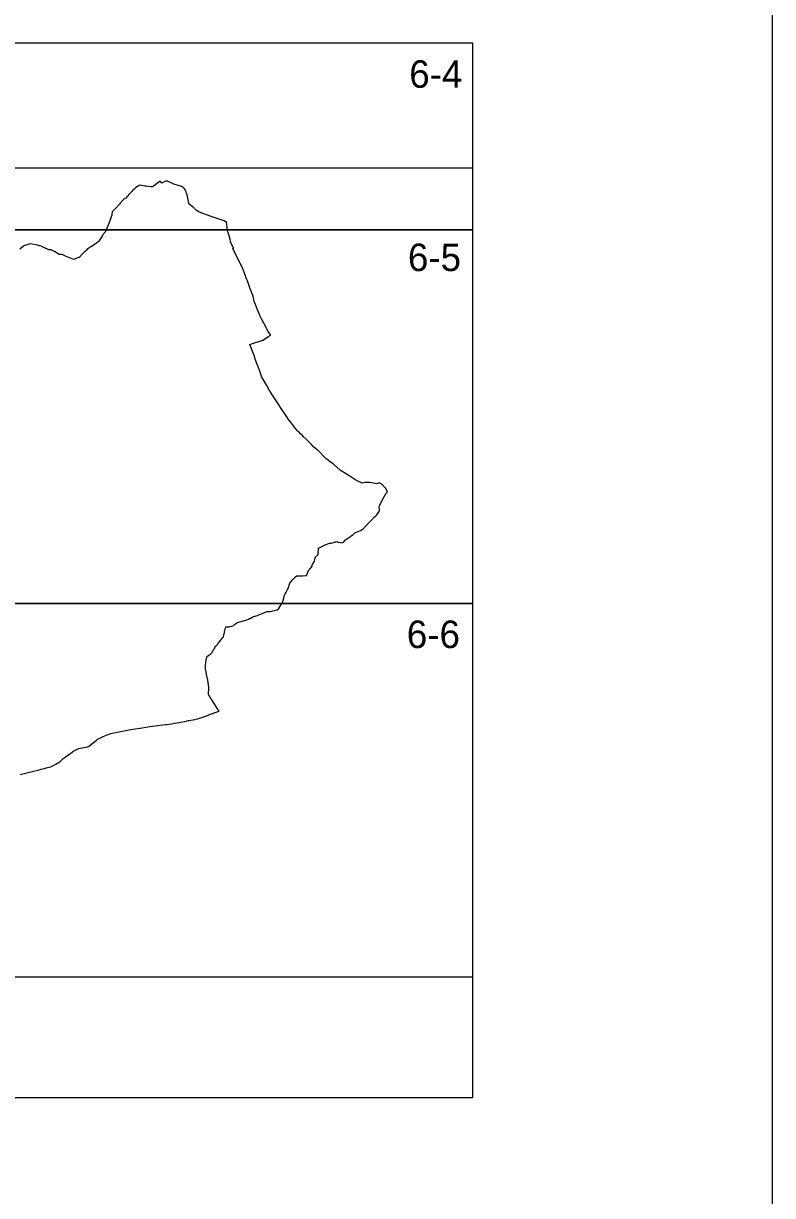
# Model space of a CAD drawing. Extents: x -447352 to -425530, y -1135906 to -1121091.
# Drawn here: x -434917.6 to -434667, y -1126663.9 to -1126271.9 of the extents above; entities that cross this region are included whole.
import ezdxf

# ---------------------------------------------------------------- set-up
doc = ezdxf.new("R2010")
doc.units = 0
for name, color, linetype in [('Vrstva 1', 7, 'Continuous'), ('Vrstva 10', 7, 'Continuous'), ('Vrstva 4', 7, 'Continuous')]:
    doc.layers.add(name, color=color, linetype=linetype)

msp = doc.modelspace()

# ---------------------------------------------------------------- linework, layer by layer
at = {"layer": 'Vrstva 1'}
msp.add_lwpolyline([(-436152.02, -1126016.81), (-436152.02, -1127066.81), (-434667.02, -1127066.81), (-434667.02, -1126016.81)], close=True, dxfattribs=at)
msp.add_lwpolyline([(-434918.73, -1126523.09), (-434915.19, -1126522.22), (-434912.42, -1126521.55), (-434911.75, -1126521.34), (-434910.26, -1126520.98), (-434910.05, -1126520.92), (-434908.62, -1126520.53), (-434908.02, -1126520.27), (-434907.8, -1126520.17), (-434907.64, -1126520.11), (-434906.82, -1126519.66), (-434906.76, -1126519.62), (-434905.45, -1126518.84), (-434904.3, -1126517.79), (-434903.65, -1126517.29), (-434903.52, -1126517.18), (-434903.5, -1126517.17), (-434903.34, -1126517.04), (-434903.19, -1126516.94), (-434902.39, -1126516.38), (-434902.33, -1126516.34), (-434902.26, -1126516.29), (-434901.75, -1126515.94), (-434901.38, -1126515.68), (-434900.72, -1126515.22), (-434900.13, -1126514.81), (-434899.97, -1126514.84), (-434899.96, -1126514.84), (-434899.94, -1126514.82), (-434899.21, -1126514.43), (-434896.25, -1126513.85), (-434895.83, -1126513.7), (-434893.8, -1126512.07), (-434893.33, -1126511.73), (-434893.3, -1126511.71), (-434892.94, -1126511.45), (-434892.76, -1126511.33), (-434891.37, -1126510.63), (-434889.96, -1126509.99), (-434889.66, -1126509.84), (-434888.4, -1126509.38), (-434887.4, -1126509.13), (-434881.69, -1126508.07), (-434880.27, -1126507.81), (-434878.56, -1126507.56), (-434874.69, -1126506.99), (-434874.45, -1126506.96), (-434870.15, -1126506.44), (-434869.62, -1126506.38), (-434867.47, -1126506.02), (-434867.15, -1126505.97), (-434865.49, -1126505.7), (-434865.09, -1126505.63), (-434863.68, -1126505.34), (-434862.39, -1126505.07), (-434862.18, -1126505.03), (-434861.01, -1126504.8), (-434860.34, -1126504.67), (-434860.32, -1126504.67), (-434859.41, -1126504.46), (-434859.34, -1126504.44), (-434858.69, -1126504.28), (-434858.34, -1126504.17), (-434857.45, -1126503.88), (-434857.01, -1126503.73), (-434856.36, -1126503.49), (-434856.24, -1126503.45), (-434855.15, -1126502.96), (-434855.15, -1126502.96), (-434855.03, -1126502.92), (-434854.38, -1126502.69), (-434854.29, -1126502.66), (-434853.86, -1126502.5), (-434852.2, -1126501.92), (-434852.22, -1126501.87), (-434852.33, -1126501.7), (-434852.49, -1126501.47), (-434852.71, -1126501.15), (-434854.41, -1126498.51), (-434854.62, -1126498.16), (-434854.79, -1126497.89), (-434855.23, -1126497.18), (-434855.76, -1126496.33), (-434855.6, -1126493.97), (-434855.59, -1126493.88), (-434855.98, -1126491.58), (-434855.98, -1126491.56), (-434855.99, -1126491.54), (-434855.99, -1126491.54), (-434855.99, -1126491.51), (-434856.4, -1126489.68), (-434856.41, -1126489.49), (-434856.47, -1126488.69), (-434856.57, -1126488.41), (-434856.58, -1126488.39), (-434856.69, -1126488.17), (-434856.73, -1126488.09), (-434856.74, -1126487.71), (-434856.77, -1126487.01), (-434856.72, -1126486.52), (-434856.72, -1126486.5), (-434856.63, -1126485.64), (-434856.61, -1126485.53), (-434856.32, -1126483.89), (-434856.24, -1126483.81), (-434855.94, -1126483.47), (-434855.88, -1126483.4), (-434855.62, -1126483.28), (-434855.56, -1126483.22), (-434855.3, -1126483.02), (-434855.07, -1126482.84), (-434854.86, -1126482.68), (-434854.8, -1126482.64), (-434854.72, -1126482.51), (-434854.64, -1126482.39), (-434854.53, -1126482.22), (-434854.31, -1126481.89), (-434853.89, -1126481.24), (-434853.76, -1126480.99), (-434853.75, -1126480.98), (-434853.61, -1126480.69), (-434853.56, -1126480.6), (-434853.38, -1126480.27), (-434853.24, -1126480.12), (-434852.94, -1126479.81), (-434852.77, -1126479.63), (-434852.49, -1126479.28), (-434852.36, -1126479.11), (-434851.67, -1126478.26), (-434851.01, -1126477.45), (-434850.72, -1126477.09), (-434850.48, -1126475.92), (-434850.42, -1126475.69), (-434850.35, -1126475.41), (-434850.03, -1126474.1), (-434849.95, -1126473.82), (-434849.95, -1126473.79), (-434849.93, -1126473.74), (-434849.77, -1126473.73), (-434849.75, -1126473.73), (-434849.51, -1126473.73), (-434848.82, -1126473.71), (-434848.81, -1126473.71), (-434848.78, -1126473.71), (-434848.1, -1126473.53), (-434847.9, -1126473.47), (-434847.48, -1126473.36), (-434847.46, -1126473.35), (-434847.4, -1126473.29), (-434847.1, -1126473.01), (-434846.98, -1126472.93), (-434846.64, -1126472.67), (-434846.22, -1126472.35), (-434846.15, -1126472.33), (-434845.59, -1126472.17), (-434842.89, -1126471.41), (-434842.3, -1126471.14), (-434841.97, -1126470.98), (-434841.92, -1126470.96), (-434841.82, -1126470.91), (-434841.46, -1126470.73), (-434841.41, -1126470.71), (-434841.38, -1126470.69), (-434841.37, -1126470.69), (-434841.34, -1126470.67), (-434841.03, -1126470.52), (-434840.97, -1126470.48), (-434840.86, -1126470.43), (-434839.78, -1126470.1), (-434839.35, -1126469.92), (-434838.83, -1126469.7), (-434837.82, -1126469.29), (-434836.4, -1126468.66), (-434836.26, -1126468.65), (-434835.13, -1126468.6), (-434832.73, -1126468.04), (-434832.2, -1126467.64), (-434832.13, -1126467.52), (-434832.04, -1126467.34), (-434831.78, -1126466.83), (-434831.43, -1126466.4), (-434831.41, -1126466.37), (-434831.2, -1126466.08), (-434831.09, -1126465.92), (-434831.08, -1126465.91), (-434830.54, -1126464.13), (-434830.53, -1126464.1), (-434830.33, -1126463.15), (-434830.07, -1126462.69), (-434829.88, -1126462.36), (-434829.33, -1126461.24), (-434828.95, -1126460.73), (-434828.92, -1126460.6), (-434828.85, -1126460.3), (-434828.82, -1126460.16), (-434828.76, -1126459.91), (-434828.74, -1126459.81), (-434828.42, -1126458.8), (-434828.41, -1126458.79), (-434828.12, -1126458.51), (-434827.46, -1126457.88), (-434827.41, -1126457.83), (-434826.94, -1126457.35), (-434826.68, -1126457.09), (-434826.58, -1126456.98), (-434826.21, -1126456.66), (-434826.17, -1126456.66), (-434826.16, -1126456.66), (-434825.75, -1126456.65), (-434825.58, -1126456.66), (-434824.95, -1126456.68), (-434824.24, -1126456.68), (-434823.27, -1126456.59), (-434823.24, -1126456.59), (-434822.99, -1126456.56), (-434822.77, -1126456.2), (-434822.72, -1126456.07), (-434822.7, -1126456.02), (-434822.68, -1126455.96), (-434822.32, -1126454.94), (-434822.18, -1126454.77), (-434822.08, -1126454.66), (-434822.04, -1126454.62), (-434821.98, -1126454.54), (-434821.86, -1126454.41), (-434821.59, -1126454.09), (-434821.5, -1126453.99), (-434821.4, -1126453.87), (-434821.06, -1126453.48), (-434820.99, -1126453.09), (-434820.93, -1126452.78), (-434820.86, -1126452.65), (-434820.31, -1126451.73), (-434820.2, -1126451.34), (-434820.01, -1126450.64), (-434819.89, -1126450.35), (-434819.6, -1126450.08), (-434819.05, -1126449.57), (-434818.98, -1126449.51), (-434818.88, -1126447.4), (-434817.86, -1126446.91), (-434817.46, -1126446.7), (-434817.21, -1126446.57), (-434816.92, -1126446.41), (-434816.7, -1126446.33), (-434816.36, -1126446.2), (-434816.31, -1126446.19), (-434815.22, -1126445.78), (-434815.21, -1126445.78), (-434814.72, -1126445.72), (-434814.64, -1126445.7), (-434813.61, -1126445.44), (-434813.46, -1126445.4), (-434813.37, -1126445.37), (-434813.2, -1126445.32), (-434812.67, -1126445.15), (-434812.67, -1126445.15), (-434812.66, -1126445.16), (-434812.66, -1126445.16), (-434812.63, -1126445.22), (-434812.5, -1126445.44), (-434811.62, -1126445.54), (-434811.42, -1126445.56), (-434811.06, -1126445.6), (-434810.97, -1126445.56), (-434810.54, -1126445.38), (-434809.89, -1126444.67), (-434808.25, -1126443.51), (-434808.16, -1126443.44), (-434807.99, -1126443.33), (-434807.48, -1126442.91), (-434806.73, -1126442.31), (-434805.46, -1126441.74), (-434804.84, -1126441.47), (-434804.3, -1126441.23), (-434804.24, -1126441.2), (-434802.59, -1126439.53), (-434801.75, -1126438.64), (-434801.39, -1126438.26), (-434800.2, -1126436.9), (-434799.6, -1126436.44), (-434799.55, -1126436.4), (-434798.71, -1126435.39), (-434798.51, -1126434.82), (-434798.6, -1126433.49), (-434798.38, -1126433), (-434797.74, -1126431.55), (-434796.28, -1126429.07), (-434796.25, -1126429.02), (-434796.25, -1126429.02), (-434796.23, -1126428.99), (-434796.2, -1126428.95), (-434796.05, -1126428.76), (-434795.79, -1126428.42), (-434796.05, -1126428.12), (-434796.19, -1126427.9), (-434796.66, -1126427.16), (-434796.86, -1126426.97), (-434797.01, -1126426.81), (-434797.2, -1126426.61), (-434797.78, -1126426.04), (-434798.63, -1126425.57), (-434799.08, -1126425.75), (-434799.41, -1126425.87), (-434801.16, -1126425.6), (-434801.77, -1126425.51), (-434801.91, -1126425.5), (-434802.5, -1126425.48), (-434802.88, -1126425.43), (-434803.04, -1126425.4), (-434803.08, -1126425.4), (-434803.11, -1126425.39), (-434803.11, -1126425.39), (-434803.14, -1126425.4), (-434803.24, -1126425.43), (-434803.37, -1126425.46), (-434804.27, -1126425.7), (-434804.34, -1126425.67), (-434806.41, -1126424.63), (-434808.43, -1126423.35), (-434811.34, -1126421.53), (-434811.5, -1126421.39), (-434811.54, -1126421.36), (-434811.63, -1126421.28), (-434812.77, -1126420.35), (-434813.92, -1126419.3), (-434814.03, -1126419.2), (-434815.24, -1126418.44), (-434815.52, -1126418.21), (-434816.15, -1126417.71), (-434816.46, -1126417.47), (-434816.96, -1126416.94), (-434817.68, -1126416.18), (-434817.83, -1126416.02), (-434818.29, -1126415.53), (-434819.26, -1126414.5), (-434819.46, -1126414.39), (-434819.46, -1126414.39), (-434819.64, -1126414.3), (-434819.84, -1126414.2), (-434820.67, -1126413.37), (-434821.3, -1126412.74), (-434822.48, -1126411.57), (-434823.41, -1126410.63), (-434823.57, -1126410.48), (-434824.01, -1126410.03), (-434824.25, -1126409.79), (-434824.34, -1126409.7), (-434824.38, -1126409.66), (-434824.9, -1126409.14), (-434825.54, -1126408.49), (-434825.62, -1126408.41), (-434825.64, -1126408.39), (-434825.79, -1126408.24), (-434826.62, -1126407.4), (-434827, -1126406.9), (-434827.28, -1126406.53), (-434827.6, -1126406.1), (-434827.96, -1126405.62), (-434828.91, -1126404.36), (-434829.28, -1126403.82), (-434831.82, -1126400.08), (-434831.99, -1126399.82), (-434832.76, -1126398.63), (-434833.43, -1126397.62), (-434834.27, -1126396.29), (-434835.07, -1126395.02), (-434835.15, -1126394.89), (-434836.24, -1126393.04), (-434837.92, -1126390.19), (-434837.92, -1126390.18), (-434837.92, -1126390.18), (-434837.93, -1126390.18), (-434838.26, -1126389.2), (-434838.71, -1126387.9), (-434838.77, -1126387.7), (-434840.15, -1126384.19), (-434840.44, -1126382.94), (-434841.92, -1126379.26), (-434841.29, -1126379.06), (-434837.57, -1126377.82), (-434835.6, -1126376.6), (-434835.42, -1126376.49), (-434835.36, -1126376.45), (-434835.16, -1126376.33), (-434834.89, -1126376.16), (-434835.81, -1126374.97), (-434837.22, -1126372.19), (-434837.97, -1126370.72), (-434838.5, -1126369.56), (-434838.52, -1126369.52), (-434838.58, -1126369.39), (-434838.59, -1126369.36), (-434838.61, -1126369.33), (-434838.65, -1126369.24), (-434838.98, -1126368.51), (-434839.3, -1126367.72), (-434840.01, -1126365.95), (-434840.42, -1126364.91), (-434840.57, -1126364.28), (-434840.83, -1126363.15), (-434841.57, -1126361.26), (-434841.77, -1126360.66), (-434842.71, -1126358.03), (-434842.98, -1126357.31), (-434844.17, -1126354.22), (-434844.24, -1126354.04), (-434844.27, -1126353.96), (-434847.62, -1126347.15), (-434847.31, -1126347.01), (-434847.29, -1126347), (-434847.39, -1126346.83), (-434847.47, -1126346.73), (-434847.64, -1126346.5), (-434847.7, -1126346.42), (-434848.31, -1126344.94), (-434848.36, -1126344.65), (-434848.46, -1126344.19), (-434848.47, -1126344.13), (-434848.98, -1126342.29), (-434849.28, -1126341.66), (-434849.29, -1126341.58), (-434849.33, -1126341.22), (-434849.47, -1126340.13), (-434849.75, -1126338.29), (-434849.81, -1126338.27), (-434850.11, -1126338.17), (-434850.49, -1126337.91), (-434850.5, -1126337.91), (-434854.8, -1126336.5), (-434857.59, -1126335.52), (-434858.9, -1126334.9), (-434859.87, -1126334.34), (-434860.59, -1126333.56), (-434862.27, -1126332.29), (-434862.33, -1126331.99), (-434862.91, -1126329.29), (-434863.06, -1126328.75), (-434863.24, -1126328.24), (-434863.29, -1126328.08), (-434863.54, -1126327.56), (-434863.79, -1126327.25), (-434864.37, -1126326.56), (-434865.12, -1126326.35), (-434867.3, -1126325.69), (-434869.39, -1126324.73), (-434870.01, -1126324.73), (-434870.96, -1126325.1), (-434871.09, -1126325.19), (-434871.16, -1126325.24), (-434871.3, -1126325.34), (-434871.34, -1126325.37), (-434871.36, -1126325.35), (-434871.57, -1126325.1), (-434871.82, -1126324.82), (-434871.9, -1126324.72), (-434871.99, -1126324.76), (-434872.5, -1126325.15), (-434872.69, -1126325.3), (-434873.36, -1126325.82), (-434874.11, -1126326.38), (-434874.45, -1126326.6), (-434875.04, -1126326.56), (-434876.52, -1126326.41), (-434876.98, -1126326.32), (-434878.57, -1126326), (-434878.87, -1126326.11), (-434879.43, -1126326.46), (-434879.98, -1126326.78), (-434880.47, -1126327.24), (-434881, -1126327.73), (-434881.4, -1126328.12), (-434881.41, -1126328.13), (-434881.74, -1126328.47), (-434881.87, -1126328.61), (-434882.38, -1126329.16), (-434882.83, -1126329.71), (-434882.99, -1126329.9), (-434883.35, -1126330.33), (-434884.09, -1126330.66), (-434884.11, -1126330.66), (-434884.31, -1126330.91), (-434885.17, -1126331.93), (-434885.55, -1126332.38), (-434886.68, -1126333.74), (-434886.69, -1126333.75), (-434887.93, -1126334.92), (-434888.05, -1126335.76), (-434888.1, -1126336.13), (-434888.14, -1126336.23), (-434888.62, -1126337.58), (-434889.06, -1126338.82), (-434889.09, -1126338.9), (-434889.39, -1126339.59), (-434890.32, -1126341.77), (-434890.34, -1126341.78), (-434890.91, -1126342.46), (-434891.21, -1126342.81), (-434891.21, -1126342.82), (-434891.55, -1126343.36), (-434892.42, -1126344.75), (-434892.51, -1126344.89), (-434892.68, -1126345.02), (-434893.21, -1126345.41), (-434893.82, -1126345.86), (-434893.82, -1126345.86), (-434894.79, -1126346.49), (-434894.92, -1126346.58), (-434895.1, -1126346.7), (-434896.4, -1126347.56), (-434896.41, -1126347.57), (-434896.67, -1126347.83), (-434896.79, -1126347.95), (-434897.01, -1126348.18), (-434897.29, -1126348.46), (-434897.86, -1126349.03), (-434899.02, -1126350.19), (-434899.22, -1126350.27), (-434900.72, -1126350.84), (-434903.53, -1126349.72), (-434903.53, -1126349.73), (-434903.54, -1126349.75), (-434904.45, -1126349.37), (-434904.76, -1126349.24), (-434904.78, -1126349.24), (-434905.17, -1126349.24), (-434905.65, -1126349.24), (-434907.21, -1126348.25), (-434907.47, -1126348.12), (-434907.76, -1126347.96), (-434907.82, -1126347.93), (-434907.86, -1126347.91), (-434908.4, -1126347.68), (-434908.45, -1126347.68), (-434908.46, -1126347.68), (-434908.61, -1126347.67), (-434908.73, -1126347.66), (-434909.04, -1126347.64), (-434909.06, -1126347.64), (-434909.06, -1126347.64), (-434909.17, -1126347.6), (-434909.41, -1126347.5), (-434910.01, -1126347.25), (-434910.17, -1126347.18), (-434911.69, -1126346.45), (-434912.31, -1126346.27), (-434912.98, -1126346.07), (-434915.3, -1126345.64), (-434915.31, -1126345.64), (-434915.71, -1126345.75), (-434917.45, -1126346.33), (-434917.58, -1126346.44), (-434918.79, -1126347.4)], dxfattribs=at)
at = {"layer": 'Vrstva 10'}
msp.add_lwpolyline([(-434767.43, -1126320.23), (-434767.43, -1126631.21), (-435100.3, -1126631.21), (-435100.3, -1126465.91), (-435079.93, -1126465.91), (-435079.93, -1126340.91), (-435079.93, -1126320.23), (-434767.43, -1126320.23)], dxfattribs=at)
at = {"layer": 'Vrstva 4'}
msp.add_line((-435079.93, -1126278.41), (-434767.43, -1126278.41), dxfattribs=at)
msp.add_lwpolyline([(-434767.43, -1126278.41), (-434767.43, -1126340.91), (-434923.68, -1126340.91), (-434923.68, -1126278.41)], dxfattribs=at)
for points in [[(-434767.43, -1126340.91), (-434767.43, -1126465.91), (-434923.68, -1126465.91), (-434923.68, -1126340.91)], [(-434767.43, -1126465.91), (-434767.43, -1126590.91), (-434923.68, -1126590.91), (-434923.68, -1126465.91)]]:
    msp.add_lwpolyline(points, close=True, dxfattribs=at)

# ---------------------------------------------------------------- texts
at = {"layer": 'Vrstva 1'}
for s, p in [('6-4', (-434788.56, -1126293.46)), ('6-5', (-434789.01, -1126354.75)), ('6-6', (-434789.38, -1126480.82))]:
    msp.add_text(s, height=9.2, dxfattribs=at).set_placement(p)

doc.saveas('drawing.dxf')
